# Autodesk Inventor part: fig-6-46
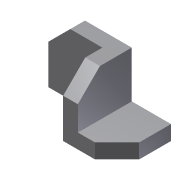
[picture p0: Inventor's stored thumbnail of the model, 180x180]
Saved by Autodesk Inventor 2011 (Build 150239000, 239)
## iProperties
Shininess: 77.0
Angle Display Precision: 2
Document Length Units: 11269
Document Angle Units: 11279
Document Time Units: 11290
Document Mass Units: 11283
Document Length Units Precision: 3
Document Angle Units Precision: 2
Created: 2001-12
Part Number: fig-6-46
Document SubType Name: Modeling
Designer: Renu Muthoo
Density: 1 g/cm^3
Density: 0.0
Volumn: 0.0
Area: 0.0
PropertySet Name: Model Information
Control State: 0
Master: False
Checked Out: False
Author: Renu Muthoo
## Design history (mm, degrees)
node "Sketch1"
sketch "Sketch2"
  geometry: L1 (16.794, 27.142)-(16.794, -22.858); L2 (16.794, -22.858)-(-27.206, -22.858); L3 (-27.206, -22.858)-(-27.206, -10.858); L4 (-27.206, -10.858)-(4.794, -10.858); L5 (4.794, -10.858)-(4.794, 27.142); L6 (4.794, 27.142)-(16.794, 27.142)
  constraints: 12 end point, 4 parallel, 2 perpendicular, 1 vertical
  dimensions: "d0" = 44 distance of L1.end L2.end; "d1" = 50 distance of L1.start L1.end; "d2" = 12 distance of L2.end L3.end
extrude "Extrusion1" new body sketch "Sketch2" distance "d3" = 44; taper "d4" = 0 deg
sketch "Sketch4"
  geometry: L1 (-16.794, -27.142)-(-16.794, 22.858) reference; L2 (27.206, 22.858)-(27.206, 10.858) reference; L3 (-16.794, -27.142)-(-61.001, -27.142); L4 (-61.001, -27.142)-(-61.001, 22.858); L5 (-61.001, 22.858)-(-16.794, 22.858)
  constraints: 6 end point, 2 perpendicular, 1 parallel
extrude "Extrusion3" join sketch "Sketch4" distance "d13" = 12; taper "d14" = 0 deg
chamfer "Chamfer3" distance "d15" = 18; stored, may be unused: second distance "d16" = 2, angle "d17" = 45 deg
body "Solid1"
